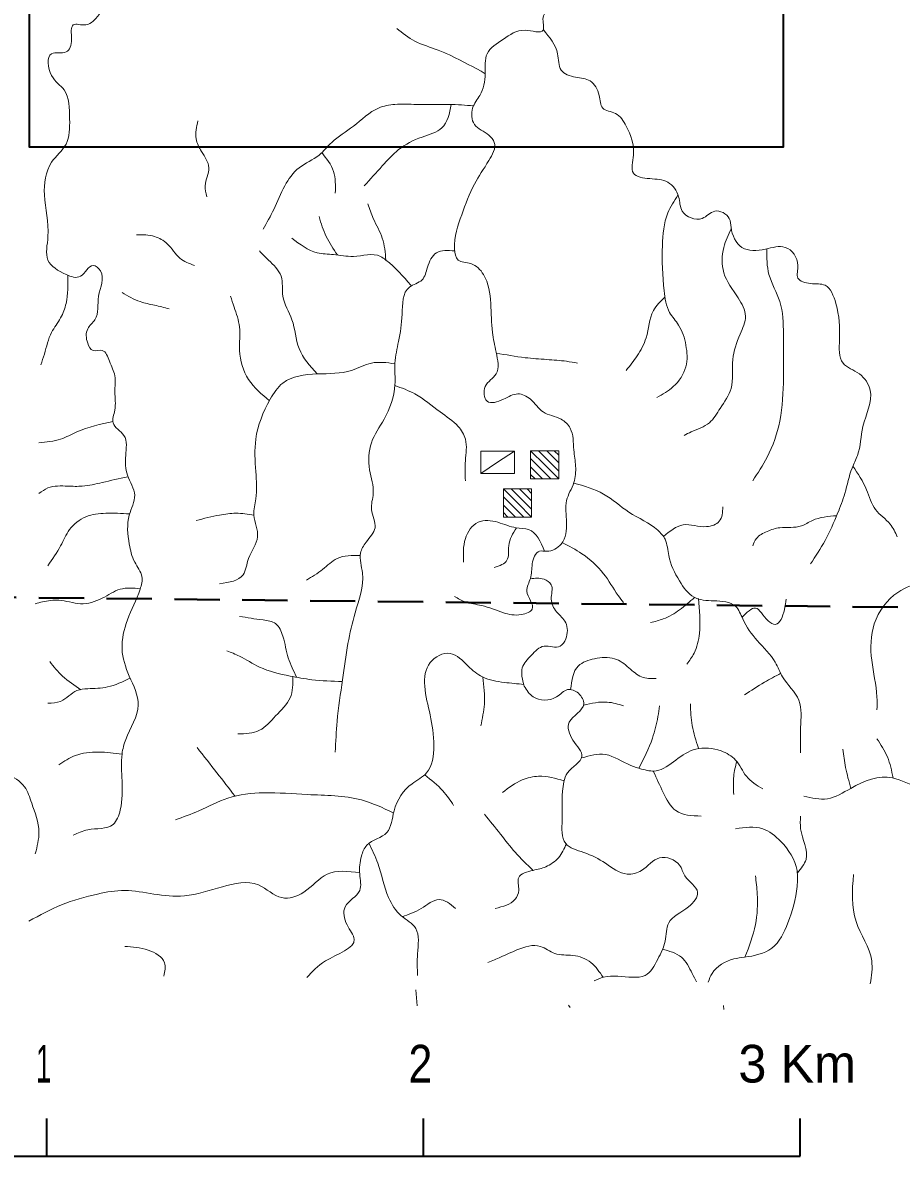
# Model space of a CAD drawing. Extents: x 788888 to 797112, y 8503144 to 8514989.
# Drawn here: x 791981 to 794313, y 8506322 to 8509330 of the extents above; entities that cross this region are included whole.
import ezdxf
from ezdxf.enums import TextEntityAlignment as Align

# ---------------------------------------------------------------- set-up
doc = ezdxf.new("R2010")
doc.units = 0
doc.header["$LTSCALE"] = 40
doc.linetypes.add('MEDIUM_DASHED', pattern=[4.5, 3, -1.5])
for name, color, linetype, lineweight in [('1', 7, 'Continuous', 13), ('15', 7, 'Continuous', 13), ('3', 7, 'Continuous', 13), ('50', 7, 'Continuous', 35), ('60', 7, 'Continuous', 35), ('63', 7, 'MEDIUM_DASHED', 40)]:
    doc.layers.add(name, color=color, linetype=linetype, lineweight=lineweight)

msp = doc.modelspace()

# ---------------------------------------------------------------- linework, layer by layer
at = {"layer": '1'}
for p, q in [((793329.39, 8508194.65), (793367.39, 8508156.65)), ((793350.39, 8508194.65), (793404.39, 8508140.65)), ((793372.39, 8508194.65), (793404.39, 8508162.65)), ((793392.39, 8508194.65), (793404.39, 8508182.65)), ((793329.39, 8508173.65), (793383.39, 8508119.65)), ((793329.39, 8508151.65), (793361.39, 8508119.65)), ((793404.39, 8508119.65), (793367.39, 8508156.65)), ((793329.39, 8508131.65), (793341.39, 8508119.65)), ((793257.23, 8508093.43), (793295.23, 8508055.43)), ((793278.23, 8508093.43), (793332.23, 8508039.43)), ((793300.23, 8508093.43), (793332.23, 8508061.43)), ((793320.23, 8508093.43), (793332.23, 8508081.43)), ((793257.23, 8508072.43), (793311.23, 8508018.43)), ((793332.23, 8508018.43), (793295.23, 8508055.43)), ((793257.23, 8508050.43), (793289.23, 8508018.43)), ((793257.23, 8508030.43), (793269.23, 8508018.43))]:
    msp.add_line(p, q, dxfattribs=at)
for points in [[(793329.39, 8508194.65), (793329.39, 8508119.65), (793404.39, 8508119.65), (793404.39, 8508194.65)], [(793257.23, 8508093.43), (793257.23, 8508018.43), (793332.23, 8508018.43), (793332.23, 8508093.43)]]:
    msp.add_lwpolyline(points, close=True, dxfattribs=at)
at = {"layer": '15'}
for p, q in [((793025.16, 8506763.82), (793028.59, 8506721.2)), ((793434.68, 8506716.72), (793430.42, 8506723.11)), ((793841.86, 8506722.63), (793842.05, 8506712.23))]:
    msp.add_line(p, q, dxfattribs=at)
for points in [[(793382.88, 8509858.32), (793362.73, 8509818.94), (793367.53, 8509790.14), (793396.31, 8509766.15), (793410.69, 8509732.55), (793415.49, 8509684.55), (793449.06, 8509607.75), (793449.06, 8509545.35), (793420.29, 8509502.15), (793401.1, 8509473.35), (793401.1, 8509420.55), (793386.71, 8509377.36), (793362.73, 8509343.76), (793362.73, 8509310.16), (793314.77, 8509310.16), (793257.22, 8509286.16), (793214.05, 8509247.76), (793209.26, 8509194.96), (793194.87, 8509137.36), (793175.68, 8509103.76), (793180.48, 8509060.57), (793218.85, 8509031.77), (793233.24, 8509012.57), (793218.85, 8508964.57), (793180.48, 8508902.17), (793146.91, 8508820.57), (793127.72, 8508729.37), (793137.31, 8508700.58), (793170.89, 8508690.98), (793204.46, 8508662.18), (793223.65, 8508585.38), (793228.44, 8508508.58), (793238.03, 8508455.78), (793238.03, 8508398.18), (793209.26, 8508364.58), (793214.05, 8508326.19), (793257.22, 8508330.99), (793295.59, 8508345.39), (793329.16, 8508330.99), (793362.73, 8508297.39), (793410.69, 8508278.19), (793434.68, 8508254.19), (793444.27, 8508196.59), (793449.06, 8508153.39), (793444.27, 8508110.19), (793425.08, 8508062.19), (793425.08, 8508004.59), (793410.69, 8507947), (793372.33, 8507927.8), (793353.14, 8507927.8), (793333.96, 8507894.2), (793329.16, 8507855.8), (793319.57, 8507822.2), (793333.96, 8507774.2), (793305.18, 8507759.8), (793257.22, 8507764.6), (793199.66, 8507783.8), (793156.5, 8507793.4), (793127.72, 8507807.8)], [(792181.45, 8509443.12), (792152.67, 8509433.52), (792114.3, 8509471.92), (792075.93, 8509481.52), (792027.97, 8509481.52), (791999.19, 8509515.12), (791965.62, 8509539.12), (791932.05, 8509577.52), (791879.29, 8509572.72), (791845.72, 8509567.92), (791826.53, 8509534.32), (791807.35, 8509495.92), (791768.98, 8509491.12), (791725.82, 8509486.32), (791692.24, 8509457.52), (791687.45, 8509414.32), (791721.02, 8509351.92), (791730.61, 8509294.32), (791721.02, 8509275.13), (791663.47, 8509270.33), (791581.93, 8509294.32), (791514.79, 8509289.52), (791452.44, 8509260.73), (791423.66, 8509217.53), (791438.05, 8509179.13), (791466.82, 8509159.93), (791457.23, 8509126.33), (791394.88, 8509107.13), (791342.12, 8509073.53), (791313.35, 8509020.73), (791303.76, 8508982.33), (791265.39, 8508967.93), (791212.63, 8508967.93), (791183.85, 8508996.73), (791183.85, 8509049.53), (791193.44, 8509092.73), (791164.67, 8509164.73), (791121.5, 8509227.13), (791078.34, 8509275.13), (791059.15, 8509294.32), (791049.56, 8509327.92), (791020.78, 8509347.12), (790992.01, 8509356.72), (790943.08, 8509433.52), (790866.34, 8509495.92), (790813.58, 8509539.12), (790784.81, 8509553.52), (790746.44, 8509577.52), (790669.7, 8509567.92), (790616.94, 8509553.52), (790559.39, 8509577.52), (790444.28, 8509591.92), (790381.93, 8509577.52), (790324.38, 8509558.32), (790281.21, 8509543.92), (790170.9, 8509558.32), (790122.94, 8509591.92), (790055.79, 8509611.12), (789993.44, 8509611.12), (789950.28, 8509606.32), (789911.91, 8509563.12), (789887.93, 8509515.12), (789868.75, 8509481.52), (789830.38, 8509476.72), (789796.8, 8509491.12), (789772.82, 8509462.32), (789782.41, 8509423.92), (789796.8, 8509385.52), (789825.58, 8509390.32), (789835.17, 8509366.32), (789839.97, 8509270.33), (789796.8, 8509183.93), (789744.05, 8509126.33), (789720.07, 8509063.93), (789748.84, 8509044.73), (789763.23, 8509001.53), (789806.4, 8508977.53), (789839.97, 8508943.93), (789883.13, 8508915.14), (789897.52, 8508881.54), (789931.1, 8508867.14), (789974.26, 8508804.74), (790007.83, 8508723.14), (789988.65, 8508627.14), (789945.48, 8508526.35), (789907.11, 8508487.95), (789873.54, 8508454.35), (789825.58, 8508372.75), (789796.8, 8508305.55), (789734.45, 8508247.95), (789700.88, 8508199.96)], [(792181.45, 8509438.32), (792197.27, 8509396.56), (792168.5, 8509334.16), (792149.31, 8509324.56), (792115.74, 8509324.56), (792110.94, 8509286.16), (792096.55, 8509252.56), (792058.18, 8509247.76), (792058.18, 8509190.16), (792091.76, 8509151.76), (792106.15, 8509074.96), (792096.55, 8509007.77), (792058.18, 8508959.77), (792039, 8508873.37), (792048.59, 8508762.97), (792048.59, 8508700.58), (792096.55, 8508662.18), (792134.92, 8508657.38), (792168.5, 8508686.18), (792187.68, 8508671.78), (792182.88, 8508604.58), (792173.29, 8508542.18), (792154.11, 8508518.18), (792154.11, 8508479.78), (792168.5, 8508460.58), (792192.48, 8508460.58), (792211.66, 8508431.78), (792226.05, 8508393.38), (792226.05, 8508350.19), (792226.05, 8508302.19), (792221.25, 8508268.59), (792250.03, 8508234.99), (792254.83, 8508182.19), (792259.62, 8508129.39), (792278.81, 8508076.59), (792264.42, 8508023.79), (792264.42, 8507947), (792278.81, 8507899), (792297.99, 8507860.6), (792293.19, 8507827), (792259.62, 8507745.4), (792245.23, 8507668.6), (792264.42, 8507596.61), (792288.4, 8507519.81), (792254.83, 8507428.61), (792245.23, 8507390.21), (792245.23, 8507318.21), (792240.44, 8507241.42), (792221.25, 8507203.02), (792154.11, 8507188.62), (792115.74, 8507174.22)], [(793209.26, 8509194.96), (793118.13, 8509242.96), (793084.56, 8509257.36), (793022.21, 8509281.36), (792974.25, 8509314.96)], [(793363.59, 8509310.89), (793401.1, 8509247.76), (793410.69, 8509204.56), (793449.06, 8509185.36), (793487.43, 8509175.76), (793511.41, 8509137.36), (793521.01, 8509103.76), (793554.58, 8509089.36), (793583.36, 8509055.77), (793602.54, 8508978.97), (793602.54, 8508930.97), (793645.7, 8508916.57), (793693.67, 8508906.97), (793722.44, 8508868.57), (793732.04, 8508830.17), (793784.79, 8508810.97), (793818.37, 8508830.17), (793856.73, 8508810.97), (793861.53, 8508786.97), (793890.31, 8508734.17), (793952.66, 8508729.37), (794005.42, 8508734.17), (794038.99, 8508686.18), (794038.99, 8508652.58), (794072.56, 8508638.18), (794110.93, 8508633.38), (794139.71, 8508585.38), (794149.3, 8508489.38), (794158.89, 8508426.98), (794202.06, 8508398.18), (794230.83, 8508354.98), (794211.65, 8508258.99), (794197.26, 8508182.19), (794182.87, 8508148.59), (794163.69, 8508081.39), (794144.5, 8508028.59), (794110.93, 8507956.6), (794072.56, 8507894.2)], [(793178.49, 8509109.69), (793113.33, 8509113.36), (793027, 8509113.36), (792969.45, 8509113.36), (792926.28, 8509103.76), (792859.14, 8509055.77), (792801.59, 8509012.57), (792768.01, 8508978.97), (792715.25, 8508945.37), (792676.89, 8508897.37), (792648.11, 8508834.97), (792619.33, 8508782.17)], [(793119.02, 8509113.17), (793094.15, 8509050.97), (793041.39, 8509026.97), (792979.04, 8508993.37), (792935.88, 8508950.17), (792887.92, 8508897.37)], [(792446.67, 8509070.16), (792441.88, 8509022.17), (792456.26, 8508988.57), (792475.45, 8508945.37), (792465.86, 8508897.37), (792470.65, 8508868.57)], [(792775.21, 8508985.9), (792806.38, 8508935.77), (792811.18, 8508878.17)], [(793720.44, 8508872.42), (793693.67, 8508825.37), (793679.28, 8508738.97), (793684.07, 8508618.98), (793698.46, 8508561.38), (793722.44, 8508527.78), (793741.63, 8508474.98), (793741.63, 8508417.38), (793708.05, 8508364.58), (793664.89, 8508335.79)], [(792945.42, 8508700.64), (792935.88, 8508758.17), (792911.9, 8508810.97), (792897.51, 8508849.37)], [(792816.77, 8508713.99), (792787.2, 8508762.97), (792768.01, 8508815.77)], [(793862.54, 8508784.2), (793842.35, 8508734.17), (793842.35, 8508666.98), (793880.72, 8508599.78), (793899.9, 8508551.78), (793885.51, 8508503.78), (793866.33, 8508436.58), (793861.53, 8508359.78), (793832.75, 8508306.99), (793803.98, 8508268.59), (793756.02, 8508244.59), (793736.83, 8508234.99)], [(792283.6, 8508767.77), (792331.56, 8508762.97), (792365.14, 8508743.77), (792398.71, 8508705.38), (792437.08, 8508686.18)], [(793011.76, 8508633.55), (792945.47, 8508700.58), (792931.08, 8508710.17), (792859.14, 8508710.17), (792806.38, 8508714.97), (792763.22, 8508719.77), (792696.07, 8508758.17)], [(792763.22, 8508398.18), (792715.25, 8508465.38), (792696.07, 8508542.18), (792672.09, 8508604.58), (792667.29, 8508657.38), (792633.72, 8508700.58), (792609.74, 8508724.57)], [(793127.54, 8508724.77), (793079.76, 8508719.77), (793055.78, 8508681.38), (793041.39, 8508647.78), (793007.82, 8508628.58), (792988.63, 8508556.58), (792979.04, 8508484.58), (792969.45, 8508426.98), (792969.45, 8508369.38), (792940.67, 8508278.19), (792907.1, 8508215.79), (792902.3, 8508143.79), (792911.9, 8508081.39), (792907.1, 8508038.19), (792916.69, 8507990.2), (792892.71, 8507951.8), (792878.32, 8507923), (792883.12, 8507870.2), (792863.93, 8507764.6), (792844.75, 8507683), (792830.36, 8507587.01), (792815.97, 8507476.61), (792811.18, 8507395.01)], [(793956.3, 8508729.52), (793962.25, 8508662.18), (793991.03, 8508590.18), (794000.62, 8508503.78), (794000.62, 8508388.58), (793991.03, 8508273.39), (793957.45, 8508177.39), (793919.08, 8508114.99)], [(792101.03, 8508660.3), (792096.55, 8508585.38), (792082.16, 8508546.98), (792058.18, 8508508.58), (792039, 8508450.98), (792029.41, 8508422.18)], [(792245.23, 8508614.18), (792293.19, 8508590.18), (792331.56, 8508580.58), (792369.93, 8508570.98)], [(792636.49, 8508327.06), (792580.96, 8508383.78), (792556.98, 8508460.58), (792556.98, 8508522.98), (792542.59, 8508575.78), (792533, 8508604.58)], [(793686.44, 8508602.79), (793655.3, 8508566.18), (793636.11, 8508494.18), (793612.13, 8508446.18), (793583.36, 8508407.78)], [(793238.32, 8508453.8), (793314.77, 8508441.38), (793372.33, 8508436.58), (793425.08, 8508431.78), (793453.86, 8508426.98)], [(792969.21, 8508425.25), (792907.1, 8508426.98), (792854.34, 8508407.78), (792763.22, 8508398.18), (792672.09, 8508374.18), (792638.52, 8508330.99), (792600.15, 8508225.39), (792600.15, 8508138.99), (792600.15, 8508066.99), (792595.35, 8508023.79), (792604.94, 8507966.2), (792580.96, 8507908.6), (792566.57, 8507865.4), (792504.22, 8507841.4)], [(792969.19, 8508367.64), (793022.21, 8508345.39), (793089.35, 8508297.39), (793137.31, 8508258.99), (793156.5, 8508225.39), (793156.5, 8508167.79), (793156.5, 8508114.99)], [(795606.72, 8507971.64), (795537.46, 8508033.67), (795509.74, 8508103), (795447.38, 8508137.67), (795378.1, 8508158.47), (795322.67, 8508241.67), (795232.6, 8508262.48), (795163.31, 8508304.08), (795121.74, 8508297.14), (795080.16, 8508255.54), (795066.31, 8508200.07), (795017.81, 8508179.27), (794969.31, 8508172.34), (794969.31, 8508116.87), (794990.09, 8508061.4), (794955.45, 8508005.93), (794872.3, 8507992.06), (794823.8, 8507985.13), (794768.37, 8507936.59), (794657.52, 8507894.99), (794567.44, 8507846.46), (794484.3, 8507853.39), (794373.44, 8507846.46), (794304.15, 8507818.72), (794241.79, 8507735.52), (794234.87, 8507638.45), (794248.72, 8507541.38), (794248.72, 8507506.71)], [(792221.34, 8508272.04), (792125.33, 8508244.59), (792082.16, 8508225.39), (792024.61, 8508215.79)], [(794184.91, 8508153.95), (794221.24, 8508090.99), (794245.22, 8508038.19), (794283.59, 8507999.8), (794302.78, 8507966.2)], [(792260.16, 8508125.63), (792192.48, 8508110.19), (792139.72, 8508100.59), (792101.35, 8508100.59), (792048.59, 8508095.79), (792024.61, 8508081.39)], [(793443.94, 8508108.71), (793523.4, 8508079.42), (793590.55, 8508031.43), (793667.28, 8507983.43), (793686.47, 8507959.43), (793696.06, 8507916.23), (793724.84, 8507849.03), (793763.21, 8507805.83), (793815.96, 8507796.23), (793873.52, 8507781.83), (793892.7, 8507748.23), (793931.07, 8507690.64), (793979.03, 8507633.04), (793998.22, 8507594.64), (794041.38, 8507532.24), (794046.18, 8507460.24), (794046.18, 8507393.04)], [(792264.82, 8508026.98), (792202.07, 8508028.59), (792149.31, 8508018.99), (792106.15, 8507985.4), (792082.16, 8507942.2), (792048.59, 8507889.4)], [(792595.32, 8508023.31), (792547.39, 8508028.59), (792504.22, 8508023.79), (792441.88, 8508009.39)], [(793682.43, 8507967.26), (793734.43, 8507997.83), (793796.78, 8507993.03), (793830.35, 8508007.43), (793839.94, 8508045.83)], [(793366.6, 8507927.83), (793324.36, 8507985.4), (793290.79, 8507990.2), (793242.83, 8508004.59), (793190.07, 8508004.59), (793156.5, 8507961.4), (793151.7, 8507899)], [(794141.85, 8508021.99), (794077.36, 8508009.39), (794048.58, 8507995), (793991.03, 8507990.2), (793957.45, 8507980.6), (793928.68, 8507961.4), (793919.08, 8507942.2)], [(793291.72, 8507989.99), (793271.61, 8507942.2), (793266.81, 8507903.8), (793233.24, 8507884.6)], [(793413.22, 8507950.67), (793465.85, 8507921.03), (793523.4, 8507868.23), (793561.77, 8507810.63), (793576.16, 8507791.43)], [(792877.02, 8507916.63), (792815.97, 8507908.6), (792777.6, 8507879.8), (792734.44, 8507851)], [(793328.98, 8507854.91), (793365.13, 8507853.41), (793384.31, 8507839.01), (793384.31, 8507800.61), (793398.7, 8507767.01), (793422.68, 8507738.21), (793422.68, 8507695.01), (793408.29, 8507675.81), (793365.13, 8507675.81), (793331.55, 8507651.81), (793307.57, 8507618.22), (793312.37, 8507570.22)], [(792293.68, 8507828.46), (792240.44, 8507827), (792192.48, 8507803), (792134.92, 8507788.6), (792077.37, 8507798.2), (792034.2, 8507793.4), (792015.02, 8507788.6)], [(793764.61, 8507805.36), (793724.84, 8507772.23), (793681.67, 8507748.23), (793648.1, 8507738.63)], [(793775.15, 8507802.58), (793777.59, 8507709.84), (793763.21, 8507657.04), (793744.02, 8507628.24)], [(793890.57, 8507751.94), (793926.27, 8507777.03), (793959.85, 8507743.43), (793979.03, 8507733.83), (794003.01, 8507772.23), (794007.81, 8507801.03)], [(792708.71, 8507592.93), (792686.48, 8507644.61), (792672.09, 8507702.2), (792652.91, 8507735.8), (792619.33, 8507745.4), (792556.98, 8507755)], [(792136.23, 8507560.4), (792086.96, 8507596.61), (792053.39, 8507635.01)], [(792829.69, 8507582.3), (792748.83, 8507587.01), (792691.27, 8507596.61), (792609.74, 8507620.61), (792556.98, 8507649.4), (792523.41, 8507663.8)], [(793311.94, 8507574.49), (793259.61, 8507579.82), (793202.06, 8507594.22), (793163.69, 8507623.02), (793115.73, 8507656.61), (793062.97, 8507632.62), (793048.58, 8507570.22), (793062.97, 8507493.42), (793072.56, 8507411.82), (793053.38, 8507339.82), (793015.01, 8507311.02), (792967.05, 8507239.03), (792947.86, 8507181.43), (792895.11, 8507147.83), (792880.72, 8507119.03), (792875.92, 8507071.03), (792875.92, 8507027.83), (792837.55, 8506984.63), (792842.35, 8506936.63), (792861.53, 8506898.24), (792784.79, 8506840.64), (792736.05, 8506796.5)], [(793435.85, 8507560.7), (793456.25, 8507623.44), (793499.42, 8507642.64), (793552.18, 8507642.64), (793590.55, 8507618.64), (793624.12, 8507594.64), (793662.49, 8507589.84)], [(792266.23, 8507590.64), (792206.86, 8507567.81), (792154.11, 8507563.01), (792125.33, 8507558.21), (792082.16, 8507529.41), (792048.59, 8507524.61)], [(792698.79, 8507595.02), (792691.27, 8507539.01), (792652.91, 8507491.01), (792609.74, 8507452.61), (792552.19, 8507443.01)], [(793202.79, 8507593.78), (793206.85, 8507522.22), (793197.26, 8507464.62)], [(793993.57, 8507603.92), (793950.26, 8507580.24), (793897.5, 8507546.64)], [(793312.37, 8507570.22), (793336.35, 8507541.42), (793398.7, 8507541.42), (793427.48, 8507560.62), (793456.25, 8507551.02), (793470.64, 8507522.22), (793432.27, 8507474.22), (793441.86, 8507426.22), (793465.85, 8507383.02), (793427.48, 8507339.82), (793417.88, 8507315.82), (793413.09, 8507215.03), (793422.68, 8507152.63), (793470.64, 8507128.63), (793528.2, 8507099.83), (793585.75, 8507071.03), (793624.12, 8507080.63), (793672.08, 8507114.23), (793724.84, 8507095.03), (793739.23, 8507066.23), (793772.8, 8507023.03), (793748.82, 8506984.63), (793696.06, 8506941.43), (793686.47, 8506893.44), (793667.28, 8506845.44), (793633.71, 8506802.24), (793600.14, 8506797.44), (793523.4, 8506797.44), (793498.33, 8506788.09)], [(793470.44, 8507519.6), (793532.99, 8507527.44), (793576.16, 8507517.84)], [(793616.97, 8507352.09), (793652.89, 8507431.44), (793667.28, 8507489.04), (793672.08, 8507517.84)], [(793774.95, 8507405.63), (793758.41, 8507465.04), (793753.61, 8507522.64)], [(794291.58, 8507326.57), (794276.44, 8507381.9), (794248.72, 8507430.44)], [(792245.12, 8507389.01), (792182.88, 8507395.01), (792120.53, 8507385.41), (792077.37, 8507361.41)], [(792544.68, 8507278.57), (792497.03, 8507339.82), (792444.27, 8507407.02)], [(793465, 8507379.4), (793528.2, 8507388.24), (793595.34, 8507359.44), (793624.12, 8507349.85), (793662.49, 8507345.05), (793715.24, 8507373.84), (793768, 8507402.64), (793835.15, 8507397.84), (793873.52, 8507373.84), (793902.29, 8507330.65), (793945.46, 8507297.05)], [(794179.43, 8507298.7), (794165.58, 8507354.17), (794158.65, 8507402.7)], [(793876.49, 8507370.52), (793868.72, 8507330.65), (793868.72, 8507282.65)], [(791694.25, 8507292.74), (791784.8, 8507322.06), (791842.36, 8507336.46), (791880.72, 8507346.06), (791938.28, 8507336.46), (791986.24, 8507302.86), (792005.42, 8507259.66), (792024.61, 8507182.86), (792015.02, 8507125.26)], [(793049.06, 8507334.43), (793096.54, 8507291.82), (793125.32, 8507253.43)], [(793655.92, 8507342.89), (793681.67, 8507287.45), (793715.24, 8507239.45), (793782.39, 8507225.05)], [(794538.91, 8507263.37), (794484.3, 8507326.43), (794442.73, 8507333.37), (794359.58, 8507305.63), (794290.3, 8507326.43), (794179.44, 8507298.7), (794117.08, 8507270.96), (794054.72, 8507277.9)], [(793418.46, 8507318.53), (793350.74, 8507330.65), (793307.57, 8507321.05), (793254.82, 8507287.45)], [(792964.59, 8507233.95), (792880.72, 8507267.83), (792736.83, 8507282.23), (792621.73, 8507287.02), (792525.8, 8507272.63), (792449.06, 8507239.03), (792386.72, 8507215.03)], [(793336.35, 8507081.05), (793288.39, 8507129.05), (793250.02, 8507177.05), (793206.85, 8507229.85)], [(794037.7, 8507074.51), (794060.57, 8507109.85), (794046.18, 8507191.45), (794046.18, 8507225.05)], [(793801.08, 8506784.75), (793811.17, 8506807.46), (793868.72, 8506845.86), (793897.5, 8506850.66), (793969.44, 8506874.66), (794012.61, 8506941.86), (794036.59, 8507037.85), (794036.59, 8507081.05), (793993.42, 8507157.85), (793945.46, 8507191.45), (793873.52, 8507191.45)], [(792900.22, 8507153.21), (792923.88, 8507099.83), (792952.66, 8507008.63), (792986.23, 8506960.63), (793024.6, 8506927.04), (793029.4, 8506859.84), (793029.4, 8506802.24)], [(793424.49, 8507151.72), (793403.5, 8507114.65), (793369.92, 8507090.65), (793336.35, 8507081.05), (793297.98, 8507061.85), (793297.98, 8507028.25), (793288.39, 8507004.25), (793235.63, 8506980.26)], [(792876.17, 8507074.86), (792789.59, 8507071.03), (792727.24, 8507023.03), (792669.69, 8507008.63), (792607.34, 8507042.23), (792511.41, 8507037.43), (792410.7, 8507013.43), (792329.16, 8507018.23), (792252.42, 8507027.83), (792180.48, 8507018.23), (792084.56, 8506989.43), (791998.23, 8506946.23)], [(793898.55, 8506850.91), (793926.27, 8506937.06), (793931.07, 8507018.65), (793926.27, 8507066.65)], [(794231.11, 8506780.01), (794234.87, 8506841.08), (794193.29, 8506945.08), (794186.37, 8507069.89)], [(792988.5, 8506958.13), (793038.99, 8506979.83), (793086.95, 8507003.83), (793130.12, 8506979.83)], [(793521.75, 8506797.12), (793489.83, 8506836.26), (793441.86, 8506855.46), (793393.9, 8506860.26), (793355.53, 8506879.46), (793293.18, 8506869.86), (793250.02, 8506850.66), (793216.45, 8506836.26)], [(792356.43, 8506800.69), (792357.94, 8506835.84), (792314.77, 8506869.44), (792252.42, 8506879.04)], [(793678.68, 8506871.76), (793729.63, 8506850.66), (793758.41, 8506807.46), (793769.92, 8506785.1)]]:
    msp.add_spline(points, degree=3, dxfattribs=at)
at = {"layer": '3'}
for p in [(793287.1, 8508193.74), (793197.1, 8508133.74)]:
    msp.add_line(p, (793242.1, 8508163.74), dxfattribs=at)
msp.add_lwpolyline([(793197.1, 8508133.74), (793287.1, 8508133.74), (793287.1, 8508193.74), (793197.1, 8508193.74)], close=True, dxfattribs=at)
at = {"layer": '50'}
msp.add_lwpolyline([(792000, 8512000), (794000, 8512000), (794000, 8509000), (792000, 8509000)], close=True, dxfattribs=at)
at = {"layer": '60'}
for p, q in [((792045.22, 8506322.26), (792045.22, 8506422.26)), ((793045.22, 8506322.26), (793045.22, 8506422.26)), ((794045.22, 8506322.26), (794045.22, 8506422.26)), ((791045.22, 8506322.26), (794045.22, 8506322.26))]:
    msp.add_line(p, q, dxfattribs=at)
at = {"layer": '63'}
msp.add_lwpolyline([(795985.61, 8513296.58), (795924.11, 8507761.4), (790507.28, 8507821.14), (790567.65, 8513356.12), (795985.61, 8513296.58)], close=True, dxfattribs=at)

# ---------------------------------------------------------------- texts
at = {"layer": '60'}
for s, width, p in [('1', 0.55, (792037.07, 8506518.1)), ('2', 0.85, (793037.07, 8506518.1))]:
    msp.add_text(s, height=100, dxfattribs=dict(at, width=width)).set_placement(p, align=Align.CENTER)
msp.add_text('3 Km', height=100, dxfattribs=at).set_placement((794037.07, 8506518.1), align=Align.CENTER)

doc.saveas('drawing.dxf')
